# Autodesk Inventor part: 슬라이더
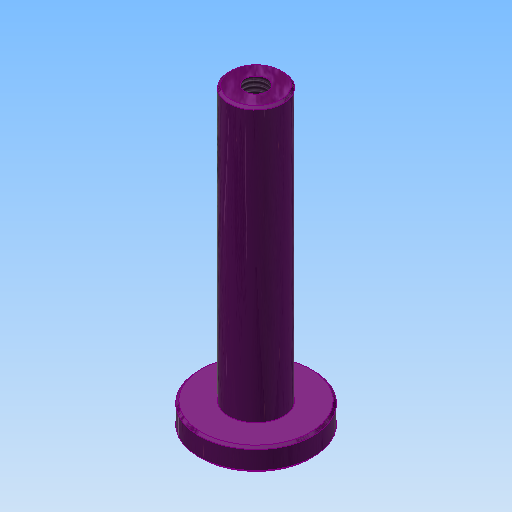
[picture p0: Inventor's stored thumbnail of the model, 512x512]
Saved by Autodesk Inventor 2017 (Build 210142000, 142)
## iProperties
Created: 2016-02
Part Number: 슬라이더
Material: 스테인리스강
Document SubType Name: Modeling
Designer: mduedu
Density: 8.08 g/cm^3
Appearance: 매끄러움 - 자주색
Author: mduedu
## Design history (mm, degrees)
sketch "스케치1"
  geometry: C1 r 12.5 at (0, 0); 1 further point
  constraints: 1 centre point, 1 coincident
  dimensions: "d0" = 25 diameter of C1
extrude "돌출1" new body sketch "스케치1" distance "d1" = 5; taper "d2" = 0 deg
sketch "스케치2"
  geometry: C1 r 6 at (0, 0); 1 further point
  constraints: 1 centre point, 1 coincident
  dimensions: "d3" = 12 diameter of C1
extrude "돌출2" join sketch "스케치2" distance "d4" = 60; taper "d5" = 0 deg
chamfer "모따기1" distance "d6" = 0.5; stored, may be unused: second distance "d7" = 2, angle "d8" = 45 deg
hole "구멍1" diameter "d11" = 4.917; stored, may be unused: countersink angle "d15" = 90 deg, drill point angle "d17" = 118 deg; dims "d9" = 10, "d10" = 10, "d12" = 10, "d13" = 4, "d14" = 2, "d16" = 12
chamfer "모따기2" distance "d18" = 0.5; stored, may be unused: second distance "d19" = 2, angle "d20" = 45 deg
node "솔리드1"
